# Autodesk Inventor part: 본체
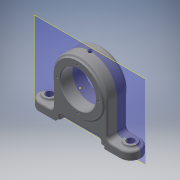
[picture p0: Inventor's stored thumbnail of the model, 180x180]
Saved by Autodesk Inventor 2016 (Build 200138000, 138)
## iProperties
Created: 2019-05
Part Number: 본체
Material: 일반
Document SubType Name: Modeling
Designer: USER
Density: 1 g/cm^3
Appearance: 기본값
Author: USER
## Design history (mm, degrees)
sketch "스케치1"
  geometry: L1 (40, 0)-(40, -48); L2 (40, -48)-(75, -48); L3 (75, -48)-(75, -60); L4 (75, -60)-(36, -60); L5 (36, -60)-(36, -56); L6 (36, -56)-(30, -56); L7 (30, -56)-(30, -50); L8 (30, -50)-(-30, -50); L9 (-30, -50)-(-30, -56); L10 (-30, -56)-(-36, -56); L11 (-36, -56)-(-36, -60); L12 (-36, -60)-(-75, -60); L13 (-75, -60)-(-75, -48); L14 (-75, -48)-(-40, -48); L15 (-40, -48)-(-40, 0); A1 r 40 centre (0, 0) between (40, 0) and (-40, 0); 1 further point
  constraints: 30 end point, 9 perpendicular, 6 point on line, 2 point on circle, 2 tangent, 1 centre point, 1 coincident, 1 horizontal, 1 vertical
  dimensions: "d0" = 80 diameter of A1; "d1" = 72 distance between parallel lines of L11 L5; "d2" = 60 distance between parallel lines of L9 L7; "d3" = 12 distance between parallel lines of L4 L2; "d4" = 4 distance between parallel lines of L4 L6; "d5" = 10 distance between parallel lines of L4 L8; "d6" = 60 distance from line of L4 point (0, 0); "d8" = 30 distance from line of point (0, 0) L7; "d9" = 75 distance from line of point (0, 0) L3; "d10" = 75 distance from line of point (0, 0) L13; "d11" = 48 distance of L14.end L15.end; "d12" = 36 distance from line of point (0, 0) L11
extrude "돌출1" new body sketch "스케치1" distance "d13" = 30; taper "d14" = 0 deg
sketch "스케치2"
  geometry: C1 r 36 at (0, 0); 1 further point
  constraints: 1 centre point, 1 coincident
  dimensions: "d15" = 72 diameter of C1
extrude "돌출2" join sketch "스케치2" distance "d16" = 3; taper "d17" = 0 deg
sketch "스케치3"
  geometry: C1 r 36 at (0, 0); 1 further point
  constraints: 1 centre point, 1 coincident
  dimensions: "d18" = 72 diameter of C1
extrude "돌출3" join sketch "스케치3" distance "d19" = 3; taper "d20" = 0 deg
sketch "스케치4"
  geometry: C1 r 26 at (0, 0); 1 further point
  constraints: 1 centre point, 1 coincident
  dimensions: "d21" = 52 diameter of C1
extrude "돌출4" cut sketch "스케치4" distance "d22" = 100; taper "d23" = 0 deg
sketch "스케치5" dims "d32" = 10
  geometry: L1 (39, 30)-(0, 30) reference; C1 r 9 at (15, 15); C2 r 9 at (135, 15); 1 further point
  constraints: 2 centre point, 1 horizontal, 2 other
  dimensions: "d24" = 60 horizontal distance of point (75, 0) C1.centre; "d25" = 15 distance from line of C1.centre L1; "d26" = 18 diameter of C1; "d29" = 120 distance of C1.centre C2.centre
extrude "돌출5" join sketch "스케치5" distance "d34" = 3; taper "d35" = 0 deg
sketch "스케치6"
  geometry: C1 r 9 at (0, 0) reference; C2 r 5.5 at (0, 0); 1 further point
  constraints: 1 centre point, 1 coincident
  dimensions: "d36" = 11 diameter of C2
extrude "돌출6" cut sketch "스케치6" distance "d37" = 50; taper "d38" = 0 deg
sketch "스케치7"
  geometry: 2 further points
  constraints: 1 vertical alignment
  dimensions: "d42" = 31 distance of point (0, 0) point (0, 31)
hole "구멍1" sketch "스케치7" at (0, 31) diameter "d43" = 3.242; stored, may be unused: countersink angle "d47" = 90 deg, drill point angle "d49" = 118 deg; dims "d44" = 6, "d45" = 4, "d46" = 2, "d48" = 8
sketch "스케치8"
  geometry: 2 further points
  constraints: 1 vertical alignment
  dimensions: "d53" = 31 distance of point (0, 0) point (0, -31)
hole "구멍2" sketch "스케치8" at (0, -31) diameter "d54" = 3.242; stored, may be unused: countersink angle "d58" = 90 deg, drill point angle "d60" = 118 deg; dims "d55" = 6, "d56" = 4, "d57" = 2, "d59" = 8
node "작업 평면1"
fillet "모깎기1" dims "d64" = 6
fillet "모깎기2" dims "d65" = 3
sketch "스케치10"
  geometry: L1 (40, 0)-(-40, 0) reference; L2 (75, 0)-(75, 30) reference; 4 further points
  constraints: 2 midpoint, 1 horizontal alignment, 1 vertical alignment
hole "구멍3" sketch "스케치10" at (0, 15) diameter "d69" = 4.917; stored, may be unused: countersink angle "d73" = 90 deg, drill point angle "d75" = 118 deg; dims "d70" = 8, "d71" = 7, "d72" = 1, "d74" = 10
sketch "스케치11"
  geometry: C1 r 1.5 at (0, 26); 2 further points
  constraints: 2 vertical alignment, 1 centre point, 1 other
  dimensions: "d76" = 3 diameter of C1
extrude "돌출7" cut sketch "스케치11" distance "d77" = 100; taper "d78" = 0 deg
sketch "스케치17"
  geometry: 1 further point
fillet "모깎기4" dims "d80" = 3
fillet "모깎기5" dims "d81" = 3
fillet "모깎기6" dims "d82" = 3
sketch "스케치18"
  geometry: L1 (30, 56)-(30, 53) reference; L2 (27, 50)-(-27, 50) reference; 2 further points
  constraints: 1 other
  dimensions: "d84" = 30 distance from line of L1 point (0, 43); "d85" = 7 distance from line of L2 point (0, 43)
feature "엠보싱1" sketch "스케치18" dims "d86" = 0.5, "d87" = 0
fillet "모깎기8" dims "d88" = 15
fillet "모깎기9" dims "d89" = 3
sketch "스케치19"
  geometry: C1 r 2.458 at (0, 15) reference; C2 r 1 at (0, 15); 1 further point
  constraints: 1 centre point, 1 coincident
  dimensions: "d90" = 2 diameter of C2
extrude "돌출8" cut sketch "스케치19" stored distance "d91" = 50; taper "d92" = 0 deg
chamfer "모따기2" distance "d93" = 1; stored, may be unused: second distance "d94" = 2, angle "d95" = 45 deg
sketch "스케치20"
  geometry: 1 further point
node "작업 평면2"
node "솔리드1"
pattern_linear "직사각형 패턴1" dims "d41" = 120
pattern_circular "원형 패턴1" dims angle "d51" = 360 deg
pattern_circular "원형 패턴2" dims angle "d62" = 360 deg
